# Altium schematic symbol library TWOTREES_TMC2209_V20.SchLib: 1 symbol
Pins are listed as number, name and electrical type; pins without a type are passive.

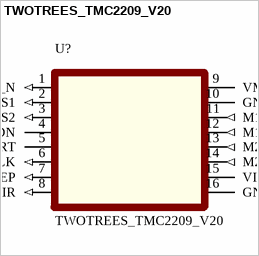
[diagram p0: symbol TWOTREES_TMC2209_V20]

## TWOTREES_TMC2209_V20
designator U?
TWOTREES TMC2209 V2.0 module, as photographed. PDN and USART separate; mechanical study Rev B.; MechanicalStatus: NOMINAL_DIMENSIONS_VERIFY_PHYSICAL_MODULE
footprint TWOTREES_TMC2209_V20_2X8 (Native PcbLib footprint with embedded STEP)
pins: 1 EN_N (in), 2 MS1 (in), 3 MS2 (in), 4 PDN, 5 USART, 6 CLK (in), 7 STEP (in), 8 DIR (in), 9 VM (power), 10 GND_POWER (power), 11 M1B (out), 12 M1A (out), 13 M2A (out), 14 M2B (out), 15 VIO (power), 16 GND_LOGIC (power)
